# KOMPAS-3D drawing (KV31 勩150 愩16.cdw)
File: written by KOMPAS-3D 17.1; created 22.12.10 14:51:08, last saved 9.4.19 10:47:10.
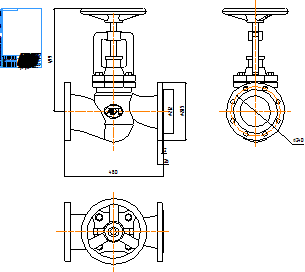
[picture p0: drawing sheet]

Title block, sheet 1: name: KV31 Ду150 Ру16; material: Внимание! Данный продукт является объектом авторского права ООО «Торговый Дом АДЛ». / Запрещается изменение, копирование, распространение / (в том числе путем копирования на другие сайты и ресурсы в Интернете) / или любое иное использование информации и объектов без предварительного / согласия правообладателя (ООО «Торговый Дом АДЛ»).; mass: 69; scale: 1:1; sheets: 1; organisation: ООО "Торговый дом АДЛ"; sheet format: A4; stored path: \\adlc.lan\data\АДЛ_ПКД\3D-модели\ADL production\Вентили ГРАНВЕНТ\KV31\KOMPAS 2D\KV31 Ду150.cdw

Views: Спереди 1, Проекционный вид 2, Проекционный вид 3
Dimensions and other numbers on the sheet: 212; 285; 480; 2; 26; 240; 499; 1:1; 1; 69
